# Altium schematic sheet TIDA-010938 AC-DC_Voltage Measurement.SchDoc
size 431 x 279 mm; Date: Not shown in title block; ApprovedBy: Not shown in title block; CheckedBy: Not shown in title block; Author: Not shown in title block; CompanyName: Not shown in title block; Engineer: Not shown in title block; Organization: Not shown in title block; Address1: Not shown in title block; Address2: Not shown in title block; Address3: Not shown in title block; Address4: Not shown in title block; DocumentNumber: 6; Revision: Use project parameter SCH_Rev; SheetNumber: 7; SheetTotal: 11; PageSetup: Record=PageOptions¦CenterHorizontal=True¦CenterVertical=True¦PrintScale=1.00¦XCorrection=1.00¦YCorrection=1.00¦PrintKind=0¦BorderSize=5000000¦LeftOffset=0¦BottomOffset=0¦Orientation=2¦PaperLength=1000¦PaperWidth=1000¦Scale=100¦PaperSource=15¦PrintQuality=600¦MediaType=1¦DitherType=10¦PaperKind=Letter¦PrintScaleMode=1
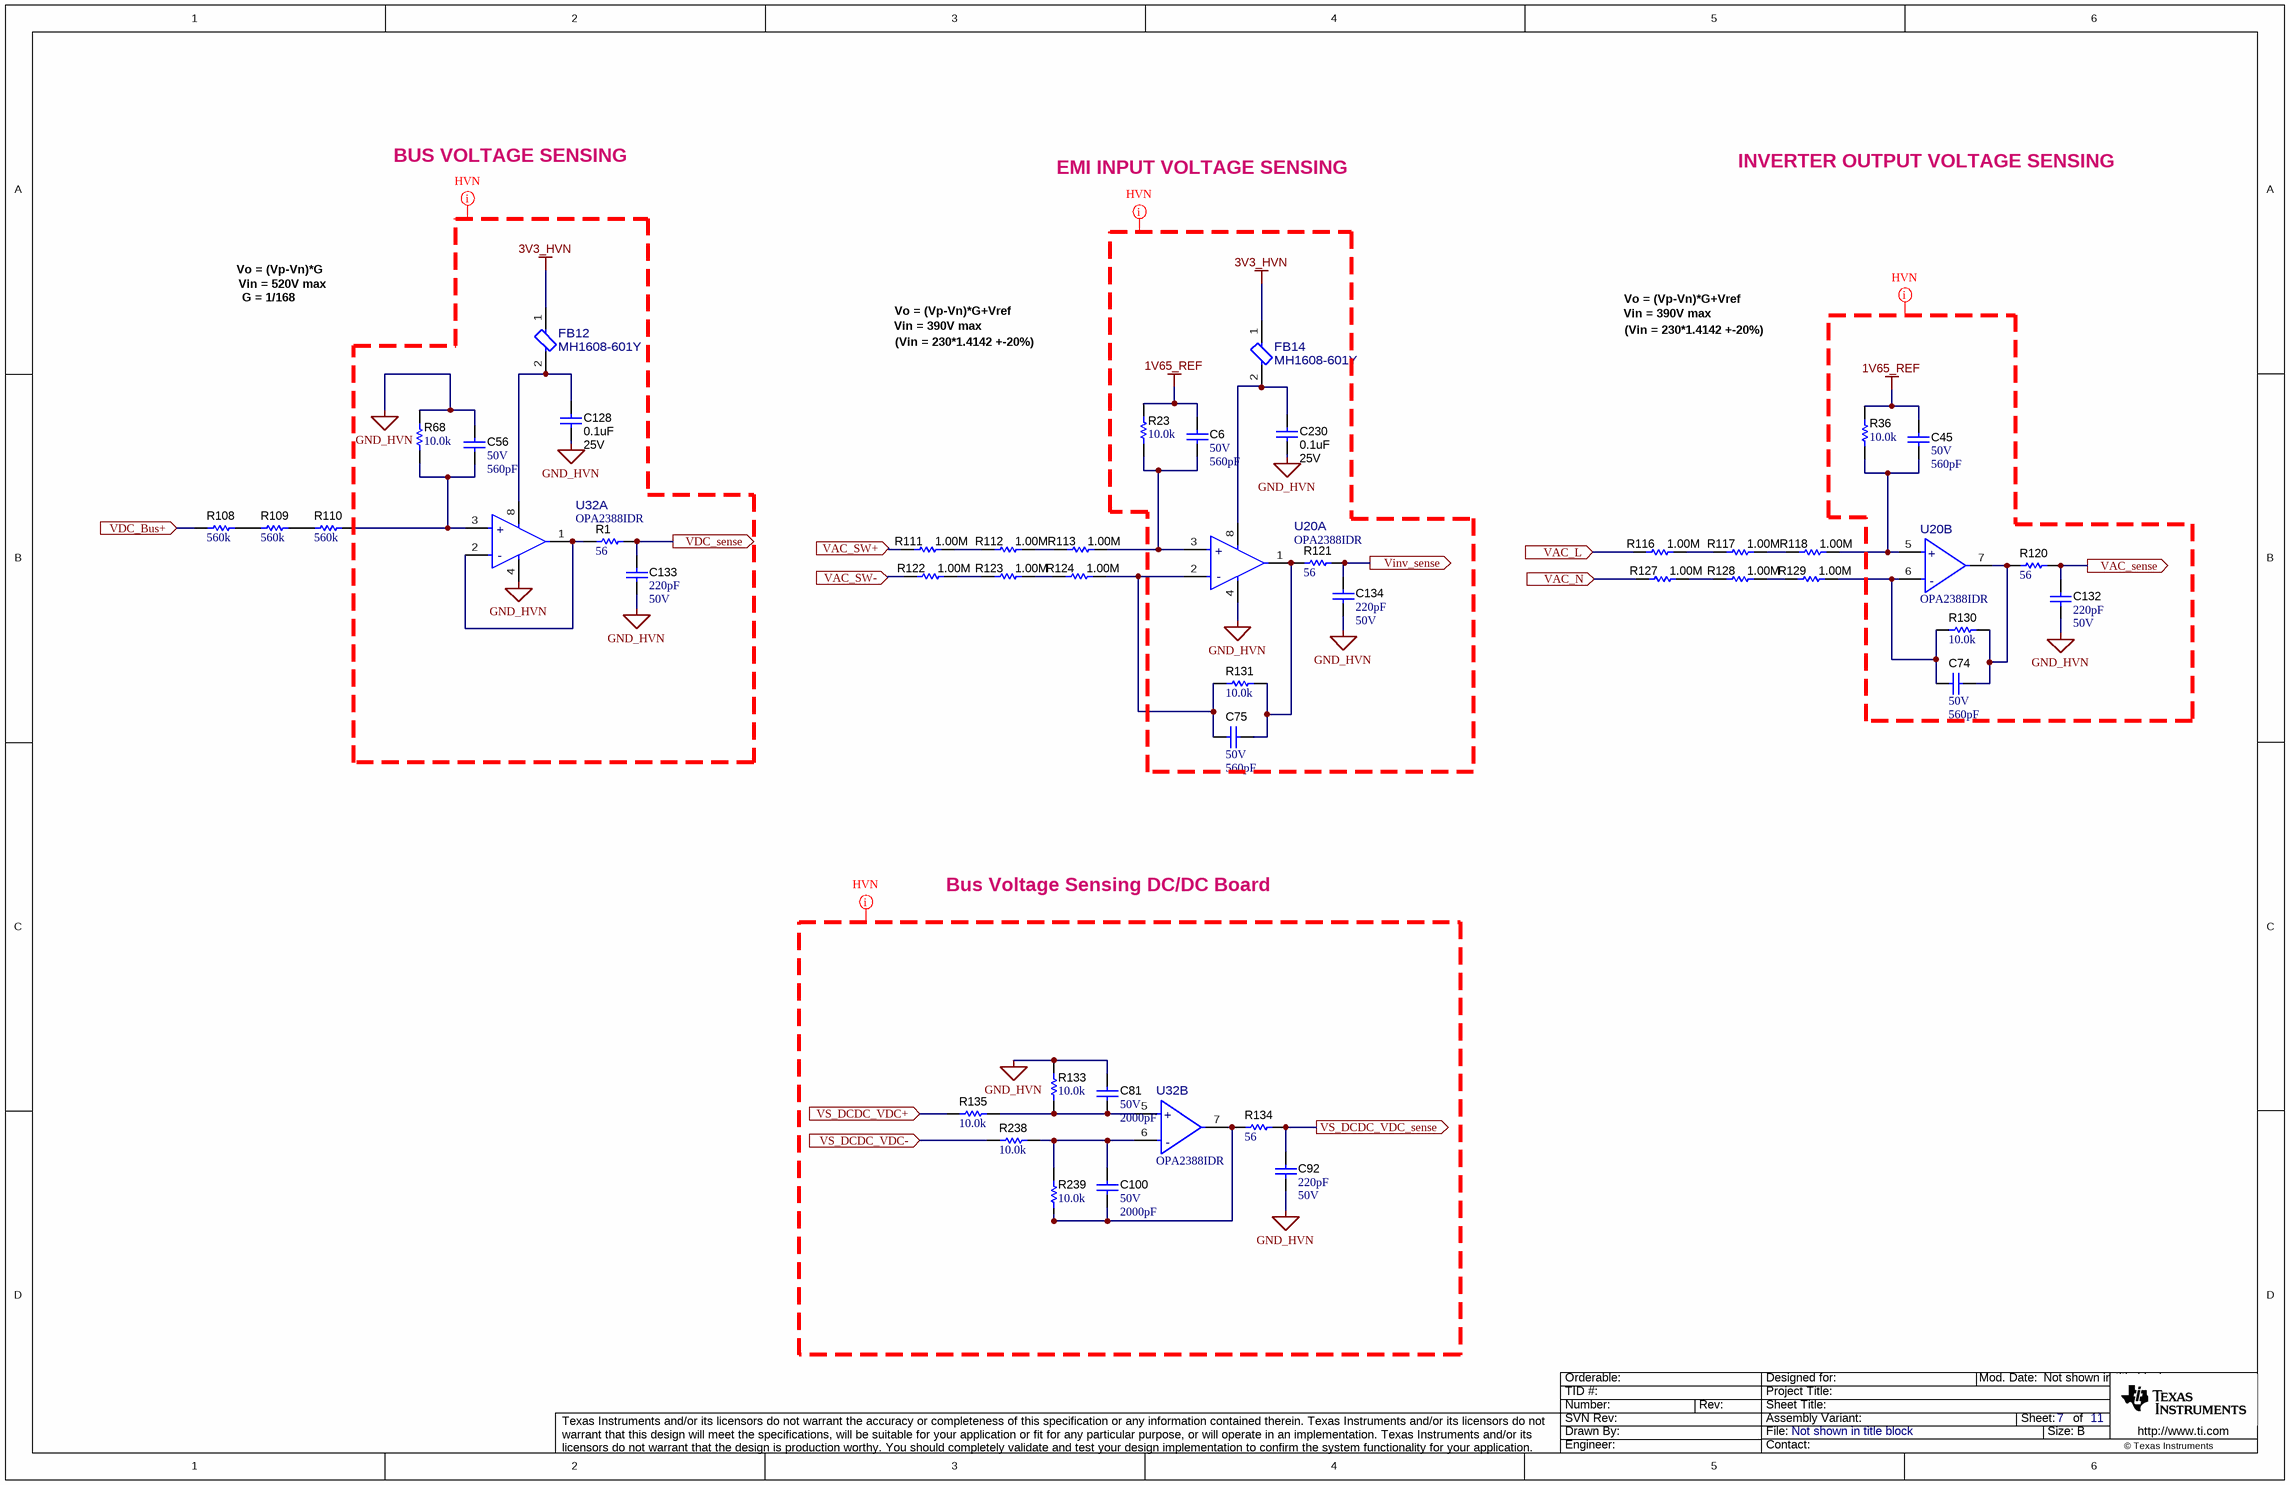
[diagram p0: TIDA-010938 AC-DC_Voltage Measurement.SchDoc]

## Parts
C6  VDC_V: 50V  ValueDisplayed: 560pF  [0603]  (hidden comment: GRM1885C1H561JA01D)
C45  VDC_V: 50V  ValueDisplayed: 560pF  [0603]  (hidden comment: GRM1885C1H561JA01D)
C56  VDC_V: 50V  ValueDisplayed: 560pF  [0603]  (hidden comment: GRM1885C1H561JA01D)
C74  VDC_V: 50V  ValueDisplayed: 560pF  [0603]  (hidden comment: GRM1885C1H561JA01D)
C75  VDC_V: 50V  ValueDisplayed: 560pF  [0603]  (hidden comment: GRM1885C1H561JA01D)
C81  VDC_V: 50V  ValueDisplayed: 2000pF  [0603]  (hidden comment: GRM1885C1H202JA01D)
C92  Cap_F: 220pF  VDC_V: 50V  [0603]  (hidden comment: GRM188R71H221KA01D)
C100  VDC_V: 50V  ValueDisplayed: 2000pF  [0603]  (hidden comment: GRM1885C1H202JA01D)
C128  ValueDisplayed: 0.1uF  VDC_V: 25V  [0603]  (hidden comment: C0603X104K3RACTU)
C132  Cap_F: 220pF  VDC_V: 50V  [0603]  (hidden comment: GRM188R71H221KA01D)
C133  Cap_F: 220pF  VDC_V: 50V  [0603]  (hidden comment: GRM188R71H221KA01D)
C134  Cap_F: 220pF  VDC_V: 50V  [0603]  (hidden comment: GRM188R71H221KA01D)
C230  ValueDisplayed: 0.1uF  VDC_V: 25V  [0603]  (hidden comment: C0603X104K3RACTU)
FB12  MH1608-601Y  [FP-MH1608-601Y_0603-MFG]
FB14  MH1608-601Y  [FP-MH1608-601Y_0603-MFG]
R1  ValueDisplayed: 56  [0603]  (hidden comment: RG1608P-560-B-T5)
R23  ValueDisplayed: 10.0k  [0603]  (hidden comment: RG1608P-103-B-T5)
R36  ValueDisplayed: 10.0k  [0603]  (hidden comment: RG1608P-103-B-T5)
R68  ValueDisplayed: 10.0k  [0603]  (hidden comment: RG1608P-103-B-T5)
R108  ValueDisplayed: 560k  [TNPV1206]  (hidden comment: TNPV1206560KBEEN)
R109  ValueDisplayed: 560k  [TNPV1206]  (hidden comment: TNPV1206560KBEEN)
R110  ValueDisplayed: 560k  [TNPV1206]  (hidden comment: TNPV1206560KBEEN)
R111  ValueDisplayed: 1.00M  [TNPV1206]  (hidden comment: TNPV12061M00BEEN)
R112  ValueDisplayed: 1.00M  [TNPV1206]  (hidden comment: TNPV12061M00BEEN)
R113  ValueDisplayed: 1.00M  [TNPV1206]  (hidden comment: TNPV12061M00BEEN)
R116  ValueDisplayed: 1.00M  [TNPV1206]  (hidden comment: TNPV12061M00BEEN)
R117  ValueDisplayed: 1.00M  [TNPV1206]  (hidden comment: TNPV12061M00BEEN)
R118  ValueDisplayed: 1.00M  [TNPV1206]  (hidden comment: TNPV12061M00BEEN)
R120  ValueDisplayed: 56  [0603]  (hidden comment: RG1608P-560-B-T5)
R121  ValueDisplayed: 56  [0603]  (hidden comment: RG1608P-560-B-T5)
R122  ValueDisplayed: 1.00M  [TNPV1206]  (hidden comment: TNPV12061M00BEEN)
R123  ValueDisplayed: 1.00M  [TNPV1206]  (hidden comment: TNPV12061M00BEEN)
R124  ValueDisplayed: 1.00M  [TNPV1206]  (hidden comment: TNPV12061M00BEEN)
R127  ValueDisplayed: 1.00M  [TNPV1206]  (hidden comment: TNPV12061M00BEEN)
R128  ValueDisplayed: 1.00M  [TNPV1206]  (hidden comment: TNPV12061M00BEEN)
R129  ValueDisplayed: 1.00M  [TNPV1206]  (hidden comment: TNPV12061M00BEEN)
R130  ValueDisplayed: 10.0k  [0603]  (hidden comment: RG1608P-103-B-T5)
R131  ValueDisplayed: 10.0k  [0603]  (hidden comment: RG1608P-103-B-T5)
R133  ValueDisplayed: 10.0k  [0603]  (hidden comment: RG1608P-103-B-T5)
R134  ValueDisplayed: 56  [0603]  (hidden comment: RG1608P-560-B-T5)
R135  ValueDisplayed: 10.0k  [0603]  (hidden comment: RG1608P-103-B-T5)
R238  ValueDisplayed: 10.0k  [0603]  (hidden comment: RG1608P-103-B-T5)
R239  ValueDisplayed: 10.0k  [0603]  (hidden comment: RG1608P-103-B-T5)
U20  OPA2388IDR  [D0008A-MFG]  (parts A,B of 2)
U32  OPA2388IDR  [D0008A-MFG]  (parts A,B of 2)

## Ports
VAC_L (in), VAC_N (in), VAC_sense (out), VAC_SW+ (in), VAC_SW- (in), VDC_Bus+ (in), VDC_sense (out), Vinv_sense (out), VS_DCDC_VDC+ (in), VS_DCDC_VDC- (in), VS_DCDC_VDC_sense (out)

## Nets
1V65_REF: C6.2 C45.2 R23.2 R36.2
3V3_HVN: FB12.1 FB14.1
GND_HVN: C56.1 C81.2 C92.1 C128.1 C132.1 C133.1 C134.1 C230.1 R68.2 R133.1 U20.4(V-) U32.4(V-)
VAC_L: R116.1 ; port VAC_L
VAC_N: R127.1 ; port VAC_N
VAC_sense: C132.2 R120.2 ; port VAC_sense
VAC_SW+: R111.1 ; port VAC_SW+
VAC_SW-: R122.1 ; port VAC_SW-
VDC_Bus+: R108.1 ; port VDC_Bus+
VDC_sense: C133.2 R1.2 ; port VDC_sense
Vinv_sense: C134.2 R121.2 ; port Vinv_sense
VS_DCDC_VDC+: R135.2 ; port VS_DCDC_VDC+
VS_DCDC_VDC-: R238.2 ; port VS_DCDC_VDC-
VS_DCDC_VDC_sense: C92.2 R134.2 ; port VS_DCDC_VDC_sense
NetC6_1: C6.1 R23.1 R113.2 U20.3(+IN_A)
NetC45_1: C45.1 R36.1 R118.2 U20.5(+IN_B)
NetC56_2: C56.2 R68.1 R110.2 U32.3(+IN_A)
NetC74_1: C74.1 R129.2 R130.2 U20.6(-IN_B)
NetC74_2: C74.2 R120.1 R130.1 U20.7(OUT_B)
NetC75_1: C75.1 R124.2 R131.2 U20.2(-IN_A)
NetC75_2: C75.2 R121.1 R131.1 U20.1(OUT_A)
NetC81_1: C81.1 R133.2 R135.1 U32.5(+IN_B)
NetC100_1: C100.1 R238.1 R239.1 U32.6(-IN_B)
NetC100_2: C100.2 R134.1 R239.2 U32.7(OUT_B)
NetC128_2: C128.2 FB12.2 U32.8(V+)
NetC230_2: C230.2 FB14.2 U20.8(V+)
NetR1_1: R1.1 U32.1(OUT_A) U32.2(-IN_A)
NetR108_2: R108.2 R109.1
NetR109_2: R109.2 R110.1
NetR111_2: R111.2 R112.1
NetR112_2: R112.2 R113.1
NetR116_2: R116.2 R117.1
NetR117_2: R117.2 R118.1
NetR122_2: R122.2 R123.1
NetR123_2: R123.2 R124.1
NetR127_2: R127.2 R128.1
NetR128_2: R128.2 R129.1

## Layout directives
net class HVN: 1V65_REF, 3V3_HVN, GND_HVN

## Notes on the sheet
- BUS VOLTAGE SENSING
- EMI INPUT VOLTAGE SENSING
- INVERTER OUTPUT VOLTAGE SENSING
- G = 1/168
- Vo = (Vp-Vn)*G
- Vin = 520V max
- Vo = (Vp-Vn)*G+Vref
- Vin = 390V max
- (Vin = 230*1.4142 +-20%)
- Bus Voltage Sensing DC/DC Board

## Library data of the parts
C6 C45 C56 C74 C75 = CMP-0007225-4: CAP, CERM, 560 pF, 50 V, +/- 5%, C0G/NP0, 0603; Manufacturer: MuRata; TaMin_C: -55°C; Polarized: N; SizeAreaWB_mm2: 4.68; Value1: Unknown; U/M: EA; Value: 560pF; TaMax_C: 125°C; SizeZ_mm: 1; SizeX_mm: 1.6; SizeY_mm: 0.8; SizeArea_mm2: 1.28; AEC Category: Q200
C81 C100 = CMP-0007195-4: CAP, CERM, 2000 pF, 50 V, +/- 5%, C0G/NP0, 0603; Manufacturer: MuRata; TaMin_C: -55°C; Polarized: N; SizeAreaWB_mm2: 4.68; Value1: Unknown; U/M: EA; Value: 2000pF; TaMax_C: 125°C; SizeZ_mm: 1; SizeX_mm: 1.6; SizeY_mm: 0.8; SizeArea_mm2: 1.28; Cap_F: 2nF; AEC Category: Q200
C92 C132-C134 = CMP-0007442-5: CAP, CERM, 220 pF, 50 V, +/- 10%, X7R, 0603; Manufacturer: MuRata; TaMin_C: -55°C; Polarized: N; SizeAreaWB_mm2: 4.68; Value1: Unknown; U/M: EA; Value: 220pF; TaMax_C: 125°C; SizeZ_mm: 1; SizeX_mm: 1.6; SizeY_mm: 0.8; SizeArea_mm2: 1.28; AEC Category: Q200
C128 C230 = CMP-0006979-5: CAP, CERM, 0.1 uF, 25 V, +/- 10%, X7R, 0603; Manufacturer: Kemet; Polarized: N; Value: 0.1uF; U/M: EA; Cap_F: 100nF; Value1: Unknown; TaMin_C: -55°C; TaMax_C: 125°C; AEC Category: Q200; SizeArea_mm2: 1.28; SizeAreaWB_mm2: 4.68; SizeX_mm: 1.6; SizeY_mm: 0.8; SizeZ_mm: 1
FB12 FB14 = CMP-0037505-1: 600 Ohms @ 100 MHz 1 Power, Signal Line Ferrite Bead 0603 (1608 Metric) 1A 200mOhm; Manufacturer: Bourns; DCR_ohm: 0.2; SizeZ_mm: 1mm; AEC Qualified: No; Impedance At Frequency: 600Ω @ 100MHz; Test Frequency: 100MHz; Tolerance_%: 25%
R1 R120 R121 R134 = CMP-0023572-3: RES, 56, 0.1%, 0.1 W, 0603; Manufacturer: Susumu Co Ltd; Power_W: 100mW; TempCo: 25 ppm/C; Value_Code: 56R0; U/M: EA; Value: 56; SizeX_mm: 1.6; SizeY_mm: 0.8; SizeZ_mm: 1; Value2: 0.1W; SizeArea_mm2: 1.28; VDC_V: 75V; AEC Category: Q200
R23 R36 R68 R130 R131 R133 R135 R238 R239 = CMP-0023404-3: RES, 10.0 k, 0.1%, 0.1 W, 0603; Manufacturer: Susumu Co Ltd; Power_W: 100mW; TempCo: 25 ppm/C; Value_Code: 10k0; U/M: EA; Value: 10.0k; EIA_Code: E192; Res_ohm: 10k; SizeX_mm: 1.6; SizeY_mm: 0.8; SizeZ_mm: 1; Value2: 0.1W; SizeArea_mm2: 1.28; VDC_V: 75V; AEC Category: Q200
R108-R110 = CMP-0018815-2: RES, 560 k, 0.1%, 1 W, 1206; Manufacturer: Vishay Draloric; Power_W: 1W; TempCo: 25 ppm/C; U/M: EA; Value: 560k; SizeX_mm: 3.2; SizeY_mm: 1.6; SizeZ_mm: 0.65; SizeArea_mm2: 5.12; AEC Qualified: N; VDC_V: 700V; AEC Category: Q200
R111-R113 R116-R118 R122-R124 R127-R129 = CMP-0018805-2: RES, 1.00 M, 0.1%, 1 W, 1206; Manufacturer: Vishay Draloric; Power_W: 1W; TempCo: 25 ppm/C; Value_Code: 1M00; U/M: EA; Value: 1.00Meg; EIA_Code: E192; Res_ohm: 1M; SizeX_mm: 3.2; SizeY_mm: 1.6; SizeZ_mm: 0.65; SizeArea_mm2: 5.12; AEC Qualified: N; VDC_V: 700V; AEC Category: Q200
U20 U32 = CMP-0097119-1: Precision, Zero-Drift, Zero-Crossover, True Rail-to-Rail, Input/Output Operational Amplifiers; Manufacturer: Texas Instruments; TJmax_C: +150°C; TaMin_C: -55°C; AEC Qualified: No; Max Dual Supply Voltage: 2.75V; Min Dual Supply Voltage: 1.25V; Input Offset Voltage: 0.00025mV; Output Current Per Channel: 30-60mA; Standoff Height: 0.11mm; Number Of Channels: 2; Min Supply Voltage: 2.5V; Input Bias Current: 0.00003uA; Nominal Supply Current: 1.7-1.9mA; Voltage Gain: 126-148dB; Bandwidth: 10MHz; SizeZ_mm: 1.75mm; Max Supply Voltage: 5.5V; Response Time: 0.75-2us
